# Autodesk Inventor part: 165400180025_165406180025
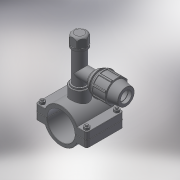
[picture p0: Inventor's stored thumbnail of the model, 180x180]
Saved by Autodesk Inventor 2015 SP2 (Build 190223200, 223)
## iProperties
Created: 2017-05
Part Number: 165400180025_165406180025
Material: Generic
Description: PLASSON TAPPER FOR PE+PVC PIPE 180-25
Document SubType Name: Modeling
Designer: KIM
Density: 1 g/cm^3
Appearance: Default
Author: KIM
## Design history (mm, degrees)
derived "16540.ipt"
feature "Solid1::16540.ipt"
feature "Solid2::16540.ipt"
tag "TaggingFeature1"
body "Solid1"
other parameters: "d0" = 198, "d1" = 245, "d4" = 154, "d5" = 0, "d6" = 12.25, "d7" = 245, "d8" = 0.1, "d10" = 0, "d11" = 1.8, "d14" = 39.3783, "d20" = 1.8, "d23" = 1.8, "d36" = 15, "d37" = 12, "d38" = 98, "d39" = 0, "d40" = 3, "d41" = 5, "d42" = 0, "d44" = 3, "d45" = 0, "d46" = 1.8, "d51" = 122, "d52" = 30.291, "d53" = 21, "d54" = 0, "d55" = 25, "d57" = 0, "d58" = 194.4, "d60" = 0, "d62" = 15, "d63" = 12, "d67" = 25, "d68" = 8.75, "d69" = 21, "d70" = 54, "d71" = 40.5, "d72" = 1.5, "d73" = 43.2, "d74" = 120 deg, "d75" = 37.5, "d76" = 10 deg, "d77" = 48.6, "d78" = 31.5, "d79" = 61, "d81" = 105, "d82" = 6.1, "d87" = 15, "d90" = 50.22, "d91" = 35 deg, "d92" = 17.5 deg, "d94" = 0, "d96" = 360 deg, "d98" = 0.5, "d99" = 67.1, "d100" = 27.2619, "d101" = 135 deg, "d102" = 1.08, "d105" = 2.7, "d106" = 0, "d107" = 0.1, "d108" = 27.2619, "d109" = 33.3201, "d111" = 26.6, "d112" = 6.65, "d113" = 3.5, "d116" = 0, "d118" = 21, "d119" = 0, "d121" = 133, "B_" = 25, "G_" = 30.291, "A_" = 122, "L_" = 245, "L_1" = 154, "l_2" = 21, "d_1" = 25, "E_" = 54, "l_" = 61, "H_" = 105, "H_2" = 133
